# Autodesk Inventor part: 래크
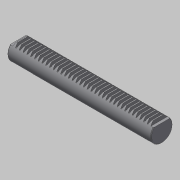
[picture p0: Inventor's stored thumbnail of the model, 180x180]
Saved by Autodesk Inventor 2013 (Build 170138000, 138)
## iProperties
Created: 2019-06
Part Number: 래크
Material: 스테인리스강
Document SubType Name: Modeling
Designer: mduedu
Density: 8.08 g/cm^3
Mass: 1739.85 g
Surface Area: 334.124 cm^2
Volume: 215.328 cm^3
Author: mduedu
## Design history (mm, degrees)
sketch "스케치1"
  geometry: L1 (0, 0)-(240, 0); L2 (240, 0)-(240, 34); L3 (240, 34)-(0, 34); L4 (0, 34)-(0, 0)
  constraints: 8 end point, 2 parallel, 1 horizontal, 1 perpendicular
  dimensions: "d0" = 240 distance of L1.start L1.end; "d1" = 34 distance of L1.end L2.end
extrude "돌출1" new body sketch "스케치1" stored distance "d2" = 36; taper "d3" = 0 deg
sketch "스케치2"
  geometry: L1 (0, 0)-(240, 0) reference; L2 (240, 0)-(240, 34) reference; L3 (240, 34)-(0, 34) reference; L4 (0, 34)-(0, 0) reference; L5 (9.44, 29.5)-(10.76, 29.5); L6 (12.398, 34)-(7.802, 34); L7 (10.1, 34)-(10.1, 29.5); L8 (7.802, 34)-(9.44, 29.5); L9 (12.398, 34)-(10.76, 29.5); L10 (8.53, 32)-(11.67, 32); 1 further point
  constraints: 12 end point, 2 midpoint, 2 point on line, 1 collinear, 1 horizontal, 1 parallel, 1 perpendicular, 1 symmetric about line
  dimensions: "d4" = 20 deg angle of L9 L7; "d5" = 2 distance between parallel lines of L10 L6; "d7" = 4.5 distance between parallel lines of L5 L6 (= 2.25 x d5); "d8" = 3.14 distance of L10.start L10.end; "d9" = 10.1 distance between parallel lines of L4 L7
extrude "돌출2" cut sketch "스케치2" stored distance "d10" = 36; taper "d11" = 0 deg
sketch "스케치3"
  geometry: L1 (235.52, 29.5)-(233.882, 34) reference; L2 (233.882, 34)-(232.198, 34) reference; L3 (232.198, 34)-(230.56, 29.5) reference; L4 (230.56, 29.5)-(229.24, 29.5) reference; L5 (229.24, 29.5)-(227.602, 34) reference; L6 (227.602, 34)-(225.918, 34) reference; L7 (225.918, 34)-(224.28, 29.5) reference; L8 (224.28, 29.5)-(222.96, 29.5) reference; L9 (222.96, 29.5)-(221.322, 34) reference; L10 (221.322, 34)-(219.638, 34) reference; L11 (219.638, 34)-(218, 29.5) reference; L12 (218, 29.5)-(216.68, 29.5) reference; L13 (216.68, 29.5)-(215.042, 34) reference; L14 (215.042, 34)-(213.358, 34) reference; L15 (213.358, 34)-(211.72, 29.5) reference; L16 (211.72, 29.5)-(210.4, 29.5) reference; L17 (210.4, 29.5)-(208.762, 34) reference; L18 (208.762, 34)-(207.078, 34) reference; L19 (207.078, 34)-(205.44, 29.5) reference; L20 (205.44, 29.5)-(204.12, 29.5) reference; L21 (204.12, 29.5)-(202.482, 34) reference; L22 (202.482, 34)-(200.798, 34) reference; L23 (200.798, 34)-(199.16, 29.5) reference; L24 (199.16, 29.5)-(197.84, 29.5) reference; L25 (197.84, 29.5)-(196.202, 34) reference; L26 (196.202, 34)-(194.518, 34) reference; L27 (194.518, 34)-(192.88, 29.5) reference; L28 (192.88, 29.5)-(191.56, 29.5) reference; L29 (191.56, 29.5)-(189.922, 34) reference; L30 (189.922, 34)-(188.238, 34) reference; L31 (188.238, 34)-(186.6, 29.5) reference; L32 (186.6, 29.5)-(185.28, 29.5) reference; L33 (185.28, 29.5)-(183.642, 34) reference; L34 (183.642, 34)-(181.958, 34) reference; L35 (181.958, 34)-(180.32, 29.5) reference; L36 (180.32, 29.5)-(179, 29.5) reference; L37 (179, 29.5)-(177.362, 34) reference; L38 (177.362, 34)-(175.678, 34) reference; L39 (175.678, 34)-(174.04, 29.5) reference; L40 (174.04, 29.5)-(172.72, 29.5) reference; L41 (172.72, 29.5)-(171.082, 34) reference; L42 (171.082, 34)-(169.398, 34) reference; L43 (169.398, 34)-(167.76, 29.5) reference; L44 (167.76, 29.5)-(166.44, 29.5) reference; L45 (166.44, 29.5)-(164.802, 34) reference; L46 (164.802, 34)-(163.118, 34) reference; L47 (163.118, 34)-(161.48, 29.5) reference; L48 (161.48, 29.5)-(160.16, 29.5) reference; L49 (160.16, 29.5)-(158.522, 34) reference; L50 (158.522, 34)-(156.838, 34) reference; L51 (156.838, 34)-(155.2, 29.5) reference; L52 (155.2, 29.5)-(153.88, 29.5) reference; L53 (153.88, 29.5)-(152.242, 34) reference; L54 (152.242, 34)-(150.558, 34) reference; L55 (150.558, 34)-(148.92, 29.5) reference; L56 (148.92, 29.5)-(147.6, 29.5) reference; L57 (147.6, 29.5)-(145.962, 34) reference; L58 (145.962, 34)-(144.278, 34) reference; L59 (144.278, 34)-(142.64, 29.5) reference; L60 (142.64, 29.5)-(141.32, 29.5) reference; L61 (141.32, 29.5)-(139.682, 34) reference; L62 (139.682, 34)-(137.998, 34) reference; L63 (137.998, 34)-(136.36, 29.5) reference; L64 (136.36, 29.5)-(135.04, 29.5) reference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; 1 further point
  constraints: 16 end point, 4 parallel, 2 horizontal, 2 perpendicular
extrude "돌출3" cut sketch "스케치3" stored distance "d18" = 36; taper "d19" = 0 deg
sketch "스케치4"
  geometry: L1 (4.48, 29.5)-(0, 29.5) reference; L2 (0, 29.5)-(0, 0) reference; L3 (0, 0)-(240, 0) reference; L4 (240, 0)-(240, 29.5) reference; L5 (240, 29.5)-(235.52, 29.5) reference; L6 (235.52, 29.5)-(233.882, 34) reference; L7 (233.882, 34)-(232.198, 34) reference; L8 (232.198, 34)-(230.56, 29.5) reference; L9 (230.56, 29.5)-(229.24, 29.5) reference; L10 (229.24, 29.5)-(227.602, 34) reference; L11 (227.602, 34)-(225.918, 34) reference; L12 (225.918, 34)-(224.28, 29.5) reference; L13 (224.28, 29.5)-(222.96, 29.5) reference; L14 (222.96, 29.5)-(221.322, 34) reference; L15 (221.322, 34)-(219.638, 34) reference; L16 (219.638, 34)-(218, 29.5) reference; L17 (218, 29.5)-(216.68, 29.5) reference; L18 (216.68, 29.5)-(215.042, 34) reference; L19 (215.042, 34)-(213.358, 34) reference; L20 (213.358, 34)-(211.72, 29.5) reference; L21 (211.72, 29.5)-(210.4, 29.5) reference; L22 (210.4, 29.5)-(208.762, 34) reference; L23 (208.762, 34)-(207.078, 34) reference; L24 (207.078, 34)-(205.44, 29.5) reference; L25 (205.44, 29.5)-(204.12, 29.5) reference; L26 (204.12, 29.5)-(202.482, 34) reference; L27 (202.482, 34)-(200.798, 34) reference; L28 (200.798, 34)-(199.16, 29.5) reference; L29 (199.16, 29.5)-(197.84, 29.5) reference; L30 (197.84, 29.5)-(196.202, 34) reference; L31 (196.202, 34)-(194.518, 34) reference; L32 (194.518, 34)-(192.88, 29.5) reference; L33 (192.88, 29.5)-(191.56, 29.5) reference; L34 (191.56, 29.5)-(189.922, 34) reference; L35 (189.922, 34)-(188.238, 34) reference; L36 (188.238, 34)-(186.6, 29.5) reference; L37 (186.6, 29.5)-(185.28, 29.5) reference; L38 (185.28, 29.5)-(183.642, 34) reference; L39 (183.642, 34)-(181.958, 34) reference; L40 (181.958, 34)-(180.32, 29.5) reference; L41 (180.32, 29.5)-(179, 29.5) reference; L42 (179, 29.5)-(177.362, 34) reference; L43 (177.362, 34)-(175.678, 34) reference; L44 (175.678, 34)-(174.04, 29.5) reference; L45 (174.04, 29.5)-(172.72, 29.5) reference; L46 (172.72, 29.5)-(171.082, 34) reference; L47 (171.082, 34)-(169.398, 34) reference; L48 (169.398, 34)-(167.76, 29.5) reference; L49 (167.76, 29.5)-(166.44, 29.5) reference; L50 (166.44, 29.5)-(164.802, 34) reference; L51 (164.802, 34)-(163.118, 34) reference; L52 (163.118, 34)-(161.48, 29.5) reference; L53 (161.48, 29.5)-(160.16, 29.5) reference; L54 (160.16, 29.5)-(158.522, 34) reference; L55 (158.522, 34)-(156.838, 34) reference; L56 (156.838, 34)-(155.2, 29.5) reference; L57 (155.2, 29.5)-(153.88, 29.5) reference; L58 (153.88, 29.5)-(152.242, 34) reference; L59 (152.242, 34)-(150.558, 34) reference; L60 (150.558, 34)-(148.92, 29.5) reference; L61 (148.92, 29.5)-(147.6, 29.5) reference; L62 (147.6, 29.5)-(145.962, 34) reference; L63 (145.962, 34)-(144.278, 34) reference; L64 (144.278, 34)-(142.64, 29.5) reference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; 1 further point
  constraints: 8 end point, 2 parallel, 1 horizontal, 1 perpendicular, 1 point on line
  dimensions: "d20" = 36 distance between parallel lines of L156 L2; "d21" = 10 distance between parallel lines of L4 L154; "d22" = 194 distance between parallel lines of L154 L156 (derived); "d23" = 4 distance between parallel lines of L3 L155
extrude "돌출4" cut sketch "스케치4" stored distance "d24" = 36; taper "d25" = 0 deg
sketch "스케치5"
  geometry: L1 (36, 0)-(0, 0) reference; C1 r 18 at (18, 18); 2 further points
  constraints: 1 centre point, 1 midpoint, 1 tangent, 1 vertical alignment
  dimensions: "d26" = 36 diameter of C1
extrude "돌출5" sketch "스케치5" stored distance "d27" = 36; taper "d28" = 0 deg
chamfer "모따기1" distance "d29" = 1; stored, may be unused: second distance "d30" = 2, angle "d31" = 45 deg
node "솔리드1"
pattern_linear "직사각형 패턴1" dims "d14" = 6.28, "d17" = 6.28
node "투영된 루프1"
node "투영된 루프2"
node "투영된 루프3"
